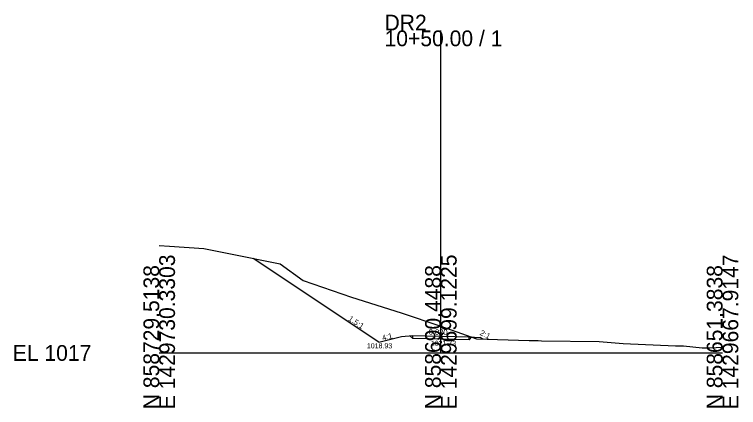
# Model space of a CAD drawing. Extents: x -26 to 103, y -10 to 3026.
# Drawn here: x -25.7 to 102.8, y 990.3 to 1060.1 of the extents above; entities that cross this region are included whole.
import ezdxf

# ---------------------------------------------------------------- set-up
doc = ezdxf.new("R2010")
doc.units = 0
for name, color, linetype in [('Default', 7, 'Continuous'), ('Exist Cross Section Cell', 7, 'Continuous'), ('Exist XS Center Line Elevation Label', 7, 'Continuous'), ('Exist XS Ground Line', 7, 'Continuous'), ('Prop CMT Pvmt Surface', 7, 'Continuous'), ('Prop CMT Shld Paved Course 1', 7, 'Continuous'), ('Prop CMT Slope Grass', 7, 'Continuous'), ('Prop CMT Subgrade Earthwork', 7, 'Continuous'), ('Prop CMT Template Flag', 7, 'Continuous'), ('Prop XS SE Text', 7, 'Continuous'), ('Prop XS Side Slope Text', 7, 'Continuous')]:
    doc.layers.add(name, color=color, linetype=linetype)

msp = doc.modelspace()

# ---------------------------------------------------------------- linework, layer by layer
at = {"layer": 'Exist Cross Section Cell'}
for p, q in [((50, 1000), (50, 1057.28)), ((0, 1000), (50, 1000)), ((50, 1000), (100, 1000))]:
    msp.add_line(p, q, dxfattribs=at)
at = {"layer": 'Exist XS Ground Line'}
msp.add_lwpolyline([(0, 1019.09), (1.8, 1018.98), (7.93, 1018.57), (12.04, 1017.73), (21.47, 1015.83), (25.57, 1012.87), (34.11, 1009.9), (42.98, 1007.13), (50, 1004.73), (53.64, 1003.48), (56.35, 1002.5), (65.66, 1002.24), (67.3, 1002.19), (67.89, 1002.18), (78.13, 1002.02), (82.39, 1001.69), (91.64, 1001.26), (93.05, 1001.29), (96.36, 1000.89), (97.72, 1000.92), (100, 1001.04)], dxfattribs=at)
at = {"layer": 'Prop CMT Pvmt Surface'}
for p, q in [((45, 1003.09), (50, 1002.99)), ((50, 1002.99), (55, 1002.89))]:
    msp.add_line(p, q, dxfattribs=at)
at = {"layer": 'Prop CMT Shld Paved Course 1'}
for points in [[(45, 1002.55), (45, 1003.09)], [(55, 1002.35), (55, 1002.89)]]:
    msp.add_lwpolyline(points, dxfattribs=at)
at = {"layer": 'Prop CMT Slope Grass'}
for p, q in [((39, 1001.93), (16.7, 1016.79)), ((39, 1001.93), (43, 1002.93)), ((43, 1002.93), (45, 1003.09)), ((55, 1002.89), (57, 1002.73)), ((57.52, 1002.47), (57, 1002.73))]:
    msp.add_line(p, q, dxfattribs=at)
at = {"layer": 'Prop CMT Subgrade Earthwork'}
for points in [[(45, 1002.55), (44.5, 1003.05)], [(55, 1002.35), (55.5, 1002.85)]]:
    msp.add_lwpolyline(points, dxfattribs=at)
at = {"layer": 'Prop CMT Template Flag'}
for p, q in [((50, 1002.45), (45, 1002.55)), ((55, 1002.35), (50, 1002.45))]:
    msp.add_line(p, q, dxfattribs=at)

# ---------------------------------------------------------------- texts
at = {"layer": 'Default'}
msp.add_text('1018.93', height=0.9, dxfattribs=at).set_placement((36.87, 1000.82))
at = {"layer": 'Exist Cross Section Cell'}
for s, p in [('DR2', (40, 1057.28)), ('10+50.00 / 1', (40, 1054.48)), ('EL 1017', (-26, 998.6))]:
    msp.add_text(s, height=2.8, dxfattribs=at).set_placement(p)
for s, p in [('E 1429730.3303', (2.8, 990)), ('E 1429699.1225', (52.8, 990)), ('E 1429667.9147', (102.8, 990)), ('N 858729.5138', (0, 990)), ('N 858690.4488', (50, 990)), ('N 858651.3838', (100, 990))]:
    msp.add_text(s, height=2.8, rotation=90, dxfattribs=at).set_placement(p)
at = {"layer": 'Exist XS Center Line Elevation Label'}
msp.add_text('1021.73', height=0.9, dxfattribs=at).set_placement((48.22, 1001.27))
at = {"layer": 'Prop XS SE Text'}
msp.add_text('0.020', height=1, rotation=358.8542, dxfattribs=at).set_placement((47.84, 1003.24))
at = {"layer": 'Prop XS Side Slope Text'}
for s, rotation, p in [('1.5:1', 326.3099, (33.46, 1005.84)), ('2:1', 333.4349, (56.82, 1003.24)), ('4:1', 14.0362, (39.69, 1002.17))]:
    msp.add_text(s, height=1, rotation=rotation, dxfattribs=at).set_placement(p)

doc.saveas('drawing.dxf')
